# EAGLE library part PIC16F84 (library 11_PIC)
MICROCONTROLLER 8-Bit PIC16F8X Family - CMOS Flash/EEPROM Pin Compatible : PIC16F83, PIC16CR83, PIC16F84A, PIC16CR84
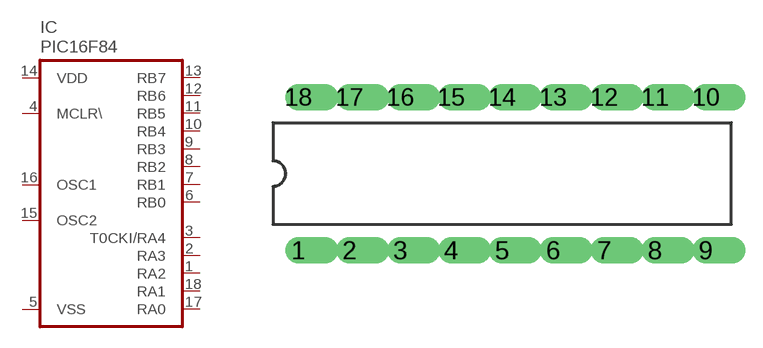
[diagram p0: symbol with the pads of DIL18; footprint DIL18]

Designator prefix IC

## PIC16F84P  [DIL18]
1  RA2
2  RA3
3  T0CKI/RA4
4  MCLR\  in
5  VSS  pwr
6  RB0
7  RB1
8  RB2
9  RB3
10  RB4
11  RB5
12  RB6
13  RB7
14  VDD  pwr
15  OSC2  out
16  OSC1  in
17  RA0
18  RA1

## Footprint DIL18 (pad centres in mm)
Dual In Line package type P
drill 0.813 offset: 1 -10.16,-3.81; 2 -7.62,-3.81; 3 -5.08,-3.81; 4 -2.54,-3.81; 5 0,-3.81; 6 2.54,-3.81; 7 5.08,-3.81; 8 7.62,-3.81; 9 10.16,-3.81; 10 10.16,3.81; 11 7.62,3.81; 12 5.08,3.81; 13 2.54,3.81; 14 0,3.81; 15 -2.54,3.81; 16 -5.08,3.81; 17 -7.62,3.81; 18 -10.16,3.81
